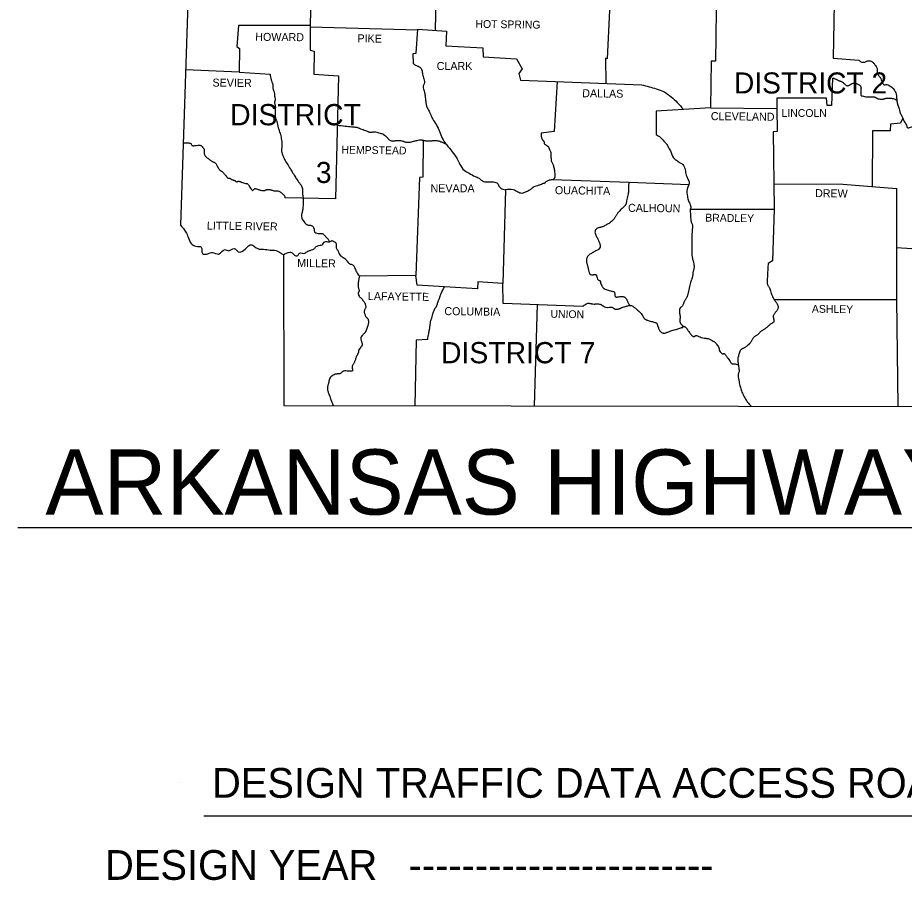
# Model space of a CAD drawing. Extents: x 535214 to 694517, y 381272 to 484355.
# Drawn here: x 655872 to 679692, y 432752 to 455929 of the extents above; entities that cross this region are included whole.
import ezdxf

# ---------------------------------------------------------------- set-up
doc = ezdxf.new("R2010")
doc.units = 0
for name, color, linetype in [('1', 7, 'Continuous'), ('2', 7, 'Continuous'), ('Default', 7, 'Continuous')]:
    doc.layers.add(name, color=color, linetype=linetype)

msp = doc.modelspace()

# ---------------------------------------------------------------- linework, layer by layer
at = {"layer": '1'}
for p, q in [((667144, 458729), (667086, 455589)), ((655872, 442234), (688934, 442234)), ((660254, 435369), (660254, 435369)), ((660875, 434480), (684515, 434480))]:
    msp.add_line(p, q, dxfattribs=at)
for points in [[(659659, 472234), (660694, 463924), (660244, 450359)], [(665191, 460852), (665184, 458804), (664934, 458799), (664954, 458649), (664714, 458654), (664709, 458544), (664474, 458544), (664479, 458464), (664129, 458454), (664124, 458149), (663784, 458179), (663729, 455719), (661804, 455724), (661759, 455154), (661829, 455104), (661824, 454464), (660383, 454528)], [(671769, 456134), (671709, 454824), (671664, 454839), (671669, 454165)], [(663729, 455684), (666624, 455608)], [(666504, 454694), (666494, 454969), (666574, 454974), (666624, 455619), (667394, 455569), (667374, 455174), (668369, 455119), (668374, 454879), (669274, 454824), (669429, 454554), (669334, 454434), (669379, 454249), (672639, 454129)], [(674489, 453504), (673758, 453459)], [(674489, 453504), (676271, 453494)], [(676271, 453494), (676274, 452869), (676169, 452864), (676199, 450789)], [(668974, 451304), (668909, 448784), (668234, 448829), (668229, 448644), (667340, 448696)], [(676199, 450789), (676149, 449399), (676039, 449329)], [(663009, 449554), (663019, 445509), (681344, 445479)], [(666889, 447284), (666579, 447264), (666546, 445504)]]:
    msp.add_lwpolyline(points, dxfattribs=at)
for points in [[(666504, 454694), (666584, 454644), (666679, 454599), (666729, 454524), (666749, 454409), (666784, 454284), (666794, 454154), (666764, 454084), (666804, 453924), (666819, 453814), (666834, 453684), (666874, 453509), (666939, 453389), (666999, 453244), (667099, 453089), (667184, 452919), (667224, 452829), (667299, 452644), (667394, 452519), (667544, 452329), (667679, 452134), (667754, 451989), (667869, 451829), (667999, 451749), (668164, 451664), (668269, 451614), (668389, 451529), (668544, 451519), (668659, 451519), (668764, 451474), (668814, 451384), (668904, 451324), (668974, 451304)], [(672639, 454129), (673029, 454019), (673229, 453944), (673429, 453799), (673594, 453654), (673758, 453459)], [(660244, 450359), (660389, 450169), (660449, 450034), (660534, 449859), (660659, 449789), (660804, 449764), (660834, 449594), (660984, 449589), (661104, 449624), (661269, 449579), (661444, 449699), (661544, 449669), (661689, 449729), (661799, 449639), (661989, 449719), (662159, 449829), (662319, 449724), (662474, 449709), (662659, 449684), (662804, 449674), (662934, 449609), (663000, 449564), (663009, 449554)], [(676039, 449329), (676024, 449174), (676019, 449029), (676009, 448889), (676007, 448837), (676007, 448810), (676009, 448784), (676020, 448754), (676037, 448726), (676055, 448698), (676069, 448669), (676104, 448559), (676139, 448464), (676209, 448339), (676225, 448315), (676242, 448292), (676259, 448269), (676274, 448244), (676300, 448177), (676302, 448142), (676294, 448109), (676254, 448039), (676236, 448013), (676217, 447987), (676197, 447961), (676179, 447934), (676171, 447889), (676182, 447836), (676190, 447786), (676174, 447744), (676164, 447735), (676153, 447727), (676130, 447713), (676106, 447700), (676084, 447684), (676028, 447633), (675999, 447608), (675969, 447584), (675904, 447539), (675834, 447494), (675814, 447476), (675796, 447456), (675778, 447434), (675759, 447414), (675733, 447395), (675704, 447378), (675675, 447361), (675649, 447339), (675627, 447310), (675609, 447278), (675591, 447245), (675569, 447214), (675549, 447189), (675527, 447164), (675479, 447119), (675404, 447069), (675378, 447053), (675352, 447038), (675312, 447014), (675299, 447004), (675281, 446984), (675270, 446959), (675254, 446904), (675241, 446858), (675229, 446812), (675221, 446766), (675219, 446719), (675226, 446652), (675234, 446584), (675254, 446464), (675252, 446427), (675242, 446389), (675232, 446352), (675229, 446314), (675254, 446149), (675279, 446019), (675319, 445904), (675374, 445774), (675407, 445713), (675444, 445654), (675507, 445569), (675576, 445489)], [(666889, 447284), (666914, 447444), (666920, 447476), (666927, 447507), (666933, 447538), (666939, 447569), (666944, 447599), (666947, 447629), (666950, 447659), (666954, 447689), (666984, 447824), (667029, 447969), (667069, 448089), (667075, 448101), (667081, 448112), (667097, 448132), (667113, 448152), (667119, 448163), (667124, 448174), (667133, 448199), (667142, 448224), (667151, 448249), (667159, 448274), (667204, 448394), (667215, 448426), (667225, 448458), (667236, 448489), (667249, 448519), (667340, 448696)]]:
    msp.add_spline(points, degree=3, dxfattribs=at)
at = {"layer": 'Default'}
for points in [[(674650, 456794), (674619, 454764), (674504, 454759), (674489, 453504)], [(677821, 456807), (677779, 454844), (678474, 454789)], [(663729, 455719), (663729, 455054), (663839, 455034), (663829, 454414), (664489, 454364), (664409, 451059), (663049, 451094)], [(661824, 454464), (662654, 454414)], [(677764, 454309), (677734, 453574), (677619, 453574), (677599, 453769), (676269, 453769), (676271, 453494)], [(670363, 454213), (670284, 452869), (669939, 452829)], [(673761, 453459), (673029, 453414), (673024, 452789)], [(679649, 453229), (679589, 453094), (679324, 453069), (679309, 452889), (678834, 452889), (678829, 451394)], [(666769, 452637), (666759, 451644), (666669, 451634), (666569, 448999)], [(670234, 451584), (672304, 451509), (673910, 451446)], [(676184, 451469), (678039, 451454), (679479, 451344)], [(679479, 451344), (679479, 448354), (679519, 445482)], [(673939, 450784), (676199, 450789)], [(679479, 449751), (680174, 449709), (680204, 449419), (680809, 449439), (680834, 449684), (681021, 449684)], [(666569, 448999), (665054, 448984)], [(667340, 448696), (666604, 448739), (666569, 448999)], [(671054, 448174), (668919, 448254), (668909, 448784)], [(676197, 448359), (679479, 448359)], [(669830, 448220), (669750, 445498)]]:
    msp.add_lwpolyline(points, dxfattribs=at)
for points in [[(678474, 454789), (678549, 454739), (678654, 454744), (678724, 454774), (678779, 454769), (678854, 454724), (678904, 454664), (678939, 454619), (678964, 454549), (678964, 454484), (678989, 454394), (679019, 454359), (679059, 454294), (679084, 454234), (679099, 454194), (679154, 454129), (679204, 454134), (679249, 454129), (679309, 454094), (679399, 454024), (679414, 454004), (679474, 453874), (679484, 453794), (679494, 453689), (679514, 453589), (679554, 453479), (679574, 453404), (679619, 453299), (679649, 453229), (679689, 453139), (679749, 453039), (679774, 452979), (679859, 452984), (679919, 453009), (679964, 453049), (680019, 453044), (680079, 453024), (680159, 453009), (680209, 453039), (680234, 453059), (680239, 453104), (680284, 453129), (680334, 453094), (680389, 453014), (680389, 452964), (680369, 452934), (680304, 452894), (680214, 452864), (680189, 452829), (680274, 452789), (680409, 452779), (680444, 452809), (680534, 452784), (680569, 452809), (680689, 452804), (680744, 452844), (680854, 452839), (680889, 452814), (680889, 452769), (680979, 452749), (681044, 452764), (681129, 452739), (681204, 452699), (681244, 452644), (681294, 452584), (681339, 452599), (681374, 452644), (681449, 452724), (681449, 452774), (681469, 452809), (681499, 452874)], [(662654, 454414), (662679, 454264), (662689, 454231), (662702, 454199), (662715, 454167), (662724, 454134), (662727, 454109), (662728, 454084), (662727, 454059), (662729, 454034), (662739, 453997), (662753, 453959), (662766, 453922), (662774, 453884), (662774, 453829), (662777, 453802), (662782, 453774), (662787, 453746), (662789, 453719), (662787, 453704), (662780, 453689), (662773, 453674), (662769, 453659), (662774, 453629), (662783, 453600), (662791, 453570), (662794, 453539), (662789, 453449), (662789, 453374), (662794, 453249), (662801, 453221), (662813, 453194), (662825, 453167), (662834, 453139), (662874, 452974), (662899, 452889), (662939, 452759), (662964, 452599), (662969, 452479), (662968, 452452), (662964, 452424), (662960, 452397), (662959, 452369), (662989, 452244), (663044, 452119), (663114, 451999), (663199, 451864), (663259, 451759), (663334, 451644), (663394, 451549), (663416, 451519), (663439, 451489), (663462, 451460), (663484, 451429), (663524, 451329), (663527, 451294), (663525, 451259), (663523, 451224), (663524, 451189), (663529, 451157), (663536, 451124), (663542, 451092), (663544, 451059), (663539, 450914), (663529, 450784), (663522, 450739), (663512, 450694), (663501, 450649), (663494, 450604), (663519, 450519), (663614, 450394), (663674, 450359), (663700, 450353), (663727, 450352), (663755, 450350), (663779, 450339), (663809, 450307), (663829, 450269), (663837, 450243), (663839, 450214), (663844, 450187), (663850, 450175), (663859, 450164), (663910, 450140), (663964, 450129), (663979, 450128), (663994, 450128), (664026, 450132), (664055, 450131), (664079, 450119), (664134, 450059), (664209, 449979), (664246, 449909)], [(677764, 454309), (677788, 454304), (677810, 454297), (677854, 454279), (677871, 454271), (677887, 454262), (677903, 454253), (677919, 454244), (677940, 454236), (677962, 454230), (677984, 454223), (678004, 454214), (678033, 454195), (678059, 454174), (678078, 454158), (678097, 454141), (678115, 454124), (678125, 454116), (678134, 454109), (678155, 454102), (678179, 454104), (678202, 454110), (678224, 454119), (678241, 454129), (678256, 454140), (678272, 454151), (678289, 454159), (678354, 454169), (678404, 454164), (678459, 454134), (678492, 454116), (678507, 454104), (678514, 454097), (678517, 454093), (678519, 454089), (678529, 454057), (678530, 454041), (678529, 454024), (678529, 453949), (678529, 453844), (678533, 453837), (678542, 453833), (678564, 453829), (678627, 453810), (678689, 453799), (678711, 453800), (678732, 453801), (678753, 453803), (678774, 453804), (678814, 453805), (678854, 453804), (678887, 453799), (678903, 453795), (678919, 453789), (678934, 453782), (678947, 453774), (678960, 453765), (678974, 453759), (679014, 453749), (679074, 453739), (679124, 453744), (679146, 453749), (679167, 453756), (679188, 453762), (679209, 453764), (679259, 453764), (679339, 453764), (679364, 453763), (679377, 453761), (679389, 453759), (679443, 453739), (679468, 453724), (679493, 453707)], [(664457, 453039), (664669, 453019), (664844, 452999), (664912, 452994), (664946, 452990), (664963, 452988), (664979, 452984), (665015, 452974), (665050, 452961), (665119, 452934), (665244, 452889), (665265, 452881), (665284, 452871), (665304, 452862), (665324, 452854), (665358, 452851), (665392, 452856), (665426, 452864), (665459, 452864), (665517, 452853), (665574, 452839), (665641, 452821), (665673, 452810), (665689, 452803), (665704, 452794), (665755, 452754), (665799, 452709), (665814, 452693), (665827, 452676), (665859, 452644), (665887, 452629), (665916, 452622), (665974, 452619), (665998, 452622), (666022, 452627), (666046, 452632), (666069, 452634), (666184, 452624), (666217, 452615), (666250, 452603), (666282, 452591), (666314, 452584), (666341, 452582), (666367, 452582), (666419, 452589), (666504, 452609), (666604, 452634), (666667, 452644), (666698, 452645), (666729, 452644), (666753, 452641), (666777, 452635), (666801, 452628), (666824, 452624), (666887, 452620), (666949, 452619), (666986, 452622), (667022, 452628), (667058, 452633), (667076, 452634), (667094, 452634), (667131, 452630), (667240, 452598), (667311, 452568), (667381, 452536)], [(669939, 452829), (669934, 452782), (669936, 452758), (669939, 452734), (669945, 452711), (669953, 452688), (669963, 452666), (669974, 452644), (669982, 452633), (669992, 452624), (670001, 452614), (670009, 452604), (670014, 452589), (670015, 452571), (670017, 452553), (670020, 452546), (670024, 452539), (670035, 452531), (670047, 452524), (670058, 452517), (670069, 452509), (670078, 452502), (670087, 452496), (670105, 452482), (670122, 452467), (670129, 452459), (670134, 452449), (670144, 452428), (670153, 452407), (670161, 452385), (670169, 452364), (670183, 452337), (670189, 452324), (670192, 452317), (670194, 452309), (670197, 452292), (670196, 452274), (670195, 452257), (670194, 452239), (670197, 452204), (670199, 452169), (670203, 452127), (670206, 452105), (670209, 452084), (670221, 452046), (670238, 452009), (670256, 451972), (670269, 451934), (670284, 451874), (670294, 451824), (670299, 451739), (670300, 451714), (670301, 451689), (670301, 451664), (670300, 451652), (670299, 451639), (670295, 451625), (670285, 451610), (670258, 451583)], [(660318, 452566), (660368, 452571), (660420, 452570), (660468, 452564), (660509, 452554), (660528, 452540), (660544, 452517), (660563, 452497), (660584, 452489), (660629, 452494), (660709, 452504), (660728, 452506), (660747, 452506), (660766, 452504), (660784, 452499), (660801, 452492), (660815, 452481), (660827, 452468), (660839, 452454), (660855, 452435), (660868, 452416), (660878, 452396), (660884, 452374), (660885, 452355), (660883, 452337), (660880, 452318), (660879, 452299), (660884, 452269), (660890, 452251), (660898, 452234), (660919, 452204), (660979, 452154), (661044, 452104), (661104, 452064), (661118, 452057), (661132, 452050), (661160, 452037), (661186, 452021), (661204, 451999), (661214, 451979), (661254, 451899), (661277, 451865), (661290, 451849), (661304, 451834), (661319, 451823), (661335, 451814), (661350, 451805), (661364, 451794), (661429, 451724), (661459, 451694), (661473, 451677), (661484, 451659), (661495, 451640), (661502, 451632), (661509, 451624), (661522, 451619), (661536, 451620), (661551, 451621), (661564, 451619), (661583, 451609), (661602, 451596), (661620, 451584), (661639, 451574), (661653, 451570), (661667, 451566), (661681, 451563), (661694, 451559), (661710, 451551), (661724, 451539), (661739, 451527), (661754, 451519), (661769, 451521), (661784, 451529), (661800, 451538), (661814, 451539), (661833, 451532), (661852, 451524), (661871, 451516), (661889, 451509), (661989, 451479), (662003, 451477), (662018, 451477), (662038, 451473), (662041, 451471), (662044, 451469), (662065, 451449), (662081, 451424), (662094, 451399), (662101, 451386), (662109, 451374), (662140, 451333), (662157, 451313), (662174, 451294), (662183, 451290), (662192, 451293), (662212, 451311), (662233, 451331), (662244, 451338), (662254, 451339), (662291, 451329), (662329, 451316), (662366, 451303), (662404, 451294), (662452, 451289), (662499, 451289), (662521, 451294), (662542, 451302), (662563, 451310), (662584, 451314), (662649, 451309), (662680, 451302), (662710, 451294), (662739, 451286), (662769, 451279), (662788, 451278), (662807, 451279), (662826, 451280), (662844, 451279), (662924, 451249), (662999, 451189), (663049, 451124), (663049, 451094)], [(673024, 452789), (673139, 452714), (673234, 452614), (673304, 452539), (673349, 452454), (673409, 452354), (673494, 452164), (673569, 452099), (673674, 452034), (673739, 451989), (673804, 451844), (673834, 451699), (673889, 451569), (673914, 451469), (673869, 451369), (673859, 451169), (673889, 451034), (673929, 450934), (673954, 450819), (673939, 450784)], [(670009, 451479), (669973, 451464), (669909, 451439), (669834, 451414), (669764, 451394), (669674, 451334), (669604, 451284), (669509, 451239), (669419, 451209), (669309, 451244), (669249, 451279), (669184, 451304), (668974, 451304)], [(670009, 451479), (670139, 451564), (670234, 451584)], [(672288, 451510), (672284, 451354), (672281, 451277), (672278, 451238), (672274, 451199), (672259, 451121), (672239, 451044), (672226, 450973), (672218, 450938), (672212, 450921), (672208, 450913), (672204, 450904), (672189, 450881), (672170, 450861), (672129, 450824), (672089, 450784), (672049, 450744), (671974, 450654), (671957, 450627), (671942, 450599), (671927, 450571), (671909, 450544), (671844, 450474), (671759, 450404), (671674, 450354), (671579, 450309), (671554, 450301), (671528, 450296), (671501, 450291), (671474, 450284), (671433, 450263), (671415, 450248), (671407, 450239), (671399, 450229), (671386, 450200), (671382, 450169), (671394, 450109), (671415, 450067), (671437, 450025), (671459, 449982), (671479, 449939), (671509, 449859), (671516, 449836), (671520, 449812), (671522, 449788), (671519, 449764), (671484, 449709), (671404, 449664), (671309, 449609), (671224, 449559), (671204, 449543), (671188, 449523), (671175, 449499), (671164, 449474), (671151, 449417), (671154, 449359), (671164, 449325), (671174, 449292), (671185, 449258), (671194, 449224), (671202, 449184), (671209, 449144), (671229, 449073), (671246, 449042), (671259, 449030), (671266, 449024), (671274, 449019), (671287, 449016), (671299, 449018), (671312, 449022), (671324, 449024), (671336, 449025), (671347, 449027), (671370, 449030), (671392, 449029), (671403, 449026), (671409, 449023), (671414, 449019), (671422, 449008), (671424, 448994), (671429, 448969), (671449, 448904), (671464, 448887), (671487, 448877), (671509, 448866), (671524, 448849), (671528, 448837), (671530, 448824), (671531, 448812), (671534, 448799), (671553, 448751), (671579, 448704), (671595, 448684), (671613, 448666), (671654, 448639), (671709, 448619), (671824, 448584), (671884, 448569), (671893, 448565), (671909, 448541), (671916, 448493), (671924, 448446), (671934, 448431), (671949, 448424), (671989, 448425), (672029, 448429), (672089, 448439), (672140, 448437), (672165, 448429), (672177, 448422), (672189, 448414), (672216, 448386), (672234, 448354), (672246, 448330), (672257, 448304), (672267, 448279), (672279, 448254), (672306, 448216), (672320, 448201)], [(673939, 450784), (673943, 450707), (673948, 450629), (673959, 450474), (673968, 450436), (673984, 450399), (673998, 450362), (674003, 450343), (674004, 450324), (674002, 450284), (673997, 450244), (673993, 450204), (673989, 450164), (673984, 450009), (673984, 449869), (673984, 449734), (673984, 449594), (673994, 449494), (674002, 449458), (674011, 449422), (674021, 449386), (674029, 449349), (674042, 449282), (674045, 449248), (674044, 449214), (674039, 449182), (674031, 449149), (674022, 449117), (674014, 449084), (674011, 449054), (674008, 449024), (674005, 448994), (673999, 448964), (673990, 448934), (673980, 448904), (673969, 448874), (673959, 448844), (673924, 448709), (673884, 448534), (673869, 448476), (673860, 448448), (673849, 448419), (673834, 448388), (673816, 448358), (673797, 448329), (673779, 448299), (673767, 448272), (673757, 448244), (673746, 448216), (673734, 448189), (673719, 448171), (673698, 448156), (673678, 448140), (673670, 448130), (673664, 448119), (673653, 448059), (673654, 447999), (673658, 447972), (673662, 447944), (673667, 447917), (673669, 447889), (673668, 447864), (673665, 447839), (673661, 447814), (673659, 447789), (673668, 447741), (673694, 447694), (673711, 447674), (673729, 447655), (673766, 447630)], [(663009, 449554), (663184, 449629), (663259, 449604), (663324, 449539), (663399, 449539), (663439, 449599), (663514, 449604), (663574, 449599), (663639, 449639), (663694, 449664), (663769, 449689), (663824, 449709), (663874, 449764), (663964, 449809), (664069, 449844), (664099, 449894), (664149, 449914), (664249, 449909), (664314, 449939), (664369, 449914), (664419, 449879), (664429, 449749), (664469, 449679), (664529, 449554), (664614, 449489), (664694, 449424), (664724, 449384), (664809, 449309), (664884, 449284), (664919, 449229), (664974, 449099), (665054, 448984)], [(665054, 448984), (665037, 448920), (665030, 448879), (665024, 448839), (665019, 448724), (665023, 448690), (665031, 448656), (665040, 448622), (665044, 448589), (665041, 448573), (665031, 448557), (665022, 448540), (665019, 448524), (665024, 448500), (665032, 448476), (665059, 448429), (665078, 448408), (665097, 448390), (665117, 448373), (665134, 448354), (665163, 448316), (665189, 448274), (665203, 448246), (665213, 448217), (665220, 448188), (665224, 448159), (665219, 448127), (665202, 448094), (665185, 448062), (665179, 448029), (665186, 447995), (665197, 447962), (665229, 447894), (665240, 447881), (665252, 447869), (665264, 447858), (665274, 447844), (665299, 447764), (665295, 447726), (665287, 447687), (665264, 447609), (665219, 447494), (665209, 447478), (665198, 447463), (665172, 447436), (665144, 447409), (665119, 447379), (665089, 447324), (665104, 447249), (665112, 447219), (665120, 447189), (665126, 447159), (665128, 447144), (665129, 447137), (665129, 447129), (665120, 447111), (665112, 447103), (665104, 447094), (665072, 447052), (665039, 447009), (665030, 446987), (665027, 446963), (665026, 446938), (665019, 446914), (665009, 446894), (664997, 446875), (664985, 446855), (664974, 446834), (664961, 446799), (664949, 446762), (664937, 446725), (664924, 446689), (664910, 446659), (664893, 446629), (664875, 446599), (664859, 446569), (664856, 446531), (664864, 446487), (664867, 446450), (664862, 446438), (664849, 446434), (664749, 446434), (664634, 446434), (664606, 446424), (664581, 446401), (664557, 446375), (664529, 446359), (664506, 446356), (664482, 446357), (664458, 446357), (664434, 446354), (664375, 446338), (664319, 446309), (664296, 446289), (664276, 446267), (664249, 446214), (664224, 446109), (664217, 446084), (664208, 446059), (664194, 446009), (664192, 445967), (664198, 445924), (664210, 445881), (664224, 445839), (664269, 445719), (664304, 445624), (664349, 445507)], [(671054, 448174), (671134, 448229), (671209, 448259), (671247, 448253), (671266, 448248), (671284, 448244), (671364, 448234), (671382, 448235), (671399, 448239), (671417, 448242), (671434, 448244), (671524, 448229), (671545, 448219), (671563, 448207), (671581, 448195), (671599, 448184), (671641, 448162), (671684, 448149), (671769, 448149), (671844, 448149), (671862, 448143), (671877, 448129), (671892, 448113), (671909, 448104), (671939, 448100), (671970, 448099), (672000, 448102), (672029, 448109), (672055, 448119), (672079, 448129), (672104, 448140), (672129, 448149), (672229, 448179), (672263, 448189), (672298, 448198), (672332, 448201), (672349, 448199), (672364, 448194), (672427, 448156), (672484, 448109), (672528, 448075), (672569, 448039), (672639, 447959), (672653, 447938), (672664, 447915), (672676, 447891), (672689, 447869), (672744, 447819), (672766, 447808), (672789, 447799), (672834, 447784), (672904, 447769), (672989, 447744), (673014, 447738), (673025, 447732), (673034, 447724), (673049, 447702), (673058, 447678), (673065, 447653), (673074, 447629), (673081, 447613), (673087, 447596), (673099, 447564), (673114, 447531), (673125, 447515), (673132, 447507), (673139, 447499), (673170, 447474), (673201, 447458), (673233, 447451), (673264, 447454), (673303, 447468), (673342, 447484), (673380, 447501), (673419, 447514), (673544, 447549), (673634, 447579), (673689, 447599), (673702, 447602), (673714, 447602), (673727, 447602), (673739, 447604), (673740, 447605), (673739, 447606), (673732, 447609), (673726, 447612), (673724, 447613), (673724, 447614), (673739, 447621), (673754, 447627), (673784, 447629), (673799, 447624), (673814, 447615), (673839, 447589), (673849, 447576), (673857, 447562), (673865, 447548), (673874, 447534), (673934, 447454), (673961, 447419), (673974, 447402), (673989, 447384), (674002, 447374), (674016, 447367), (674030, 447362), (674044, 447359), (674058, 447364), (674072, 447375), (674085, 447387), (674099, 447389), (674174, 447364), (674239, 447339), (674314, 447319), (674331, 447317), (674347, 447316), (674363, 447316), (674379, 447314), (674464, 447294), (674529, 447259), (674589, 447224), (674649, 447159), (674709, 447059), (674716, 447040), (674720, 447020), (674723, 446999), (674729, 446979), (674759, 446935), (674778, 446916), (674799, 446899), (674815, 446896), (674834, 446901), (674851, 446905), (674864, 446899), (674889, 446867), (674913, 446835), (674959, 446769), (674994, 446719), (675027, 446671), (675046, 446649), (675057, 446639), (675069, 446629), (675083, 446625), (675097, 446626), (675111, 446629), (675124, 446629), (675231, 446609)]]:
    msp.add_spline(points, degree=3, dxfattribs=at)

# ---------------------------------------------------------------- texts
at = {"layer": '1'}
msp.add_text('DESIGN TRAFFIC DATA ACCESS ROAD', height=800, dxfattribs=at).set_placement((661094, 434969))
at = {"layer": '2'}
for s, height, p in [('ARKANSAS HIGHWAY DISTRICT 4', 1750, (656617, 442579)), ('DESIGN YEAR', 800, (658220, 432764)), ('-----------------------', 800, (666374, 432764))]:
    msp.add_text(s, height=height, dxfattribs=at).set_placement(p)
at = {"layer": 'Default'}
for s, height, rotation, p in [('HOT SPRING', 210, 359.2216, (668169, 455659)), ('HOWARD', 215, 359.5145, (662254, 455309)), ('PIKE', 215, 359.0452, (664999, 455269)), ('SEVIER', 215, 359.4271, (661104, 454079)), ('DALLAS', 215, 359.2462, (671039, 453794)), ('CLEVELAND', 215, 359.3377, (674494, 453179)), ('HEMPSTEAD', 210, 359.1885, (664569, 452279)), ('OUACHITA', 215, 359.2043, (670304, 451189)), ('DREW', 215, 359.2258, (677294, 451109)), ('CALHOUN', 215, 359.3634, (672269, 450714)), ('BRADLEY', 210, 359.1449, (674344, 450454)), ('LITTLE RIVER', 215.03, 359.1697, (660954, 450239)), ('MILLER', 215, 359.132, (663379, 449234)), ('LAFAYETTE', 215, 359.1839, (665279, 448344)), ('COLUMBIA', 215, 359.2125, (667334, 447939)), ('UNION', 210, 358.9584, (670184, 447869)), ('ASHLEY', 210, 359.2361, (677209, 448004))]:
    msp.add_text(s, height=height, rotation=rotation, dxfattribs=at).set_placement(p)
for s, height, p in [('CLARK', 215, (667129, 454524)), ('DISTRICT 2', 565, (675117, 453894)), ('DISTRICT', 570, (661579, 453039)), ('LINCOLN', 210, (676394, 453264)), ('3', 565, (663884, 451489)), ('NEVADA', 215, (666964, 451239)), ('DISTRICT 7', 570, (667244, 446644))]:
    msp.add_text(s, height=height, dxfattribs=at).set_placement(p)

doc.saveas('drawing.dxf')
